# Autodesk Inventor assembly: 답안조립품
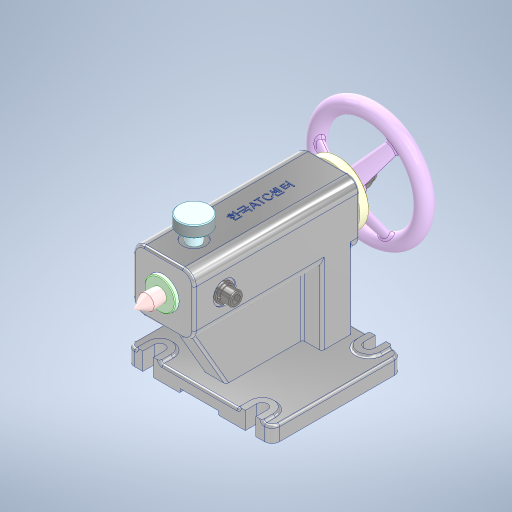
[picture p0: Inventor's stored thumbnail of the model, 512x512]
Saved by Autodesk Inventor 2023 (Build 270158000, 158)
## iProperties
Created: 2024-07
Part Number: 답안조립품
Document SubType Name: Assembly
Designer: home
Author: home
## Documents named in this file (15)
- C:\Users\home\Desktop\740704V1008\답안조립품.iam
- C:\Users\home\Desktop\740704V1008\본체.ipt
- C:\Users\home\Desktop\740704V1008\나사축.ipt
- C:\Users\home\Desktop\740704V1008\부시.ipt
- C:\Users\home\Desktop\740704V1008\센터.ipt
- C:\Users\home\Desktop\740704V1008\스러스트 볼 베어링 51101.ipt
- C:\Users\home\Desktop\740704V1008\스톱퍼.ipt
- C:\Users\home\Desktop\740704V1008\스프링  와셔 M12.ipt
- C:\Users\home\Desktop\740704V1008\슬리브.ipt
- C:\Users\home\Desktop\740704V1008\육각 소켓 머리 볼트 M6x12.ipt
- C:\Users\home\Desktop\740704V1008\육각 소켓 머리 볼트 M12x16.ipt
- C:\Users\home\Desktop\740704V1008\캡너트 M12.ipt
- C:\Users\home\Desktop\740704V1008\평와셔 M12.ipt
- C:\Users\home\Desktop\740704V1008\핸들.ipt
- C:\Users\home\Desktop\740704V1008\평행키 4x4x14.ipt
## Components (1 placed, 1 different names)
1. 핸들:1
